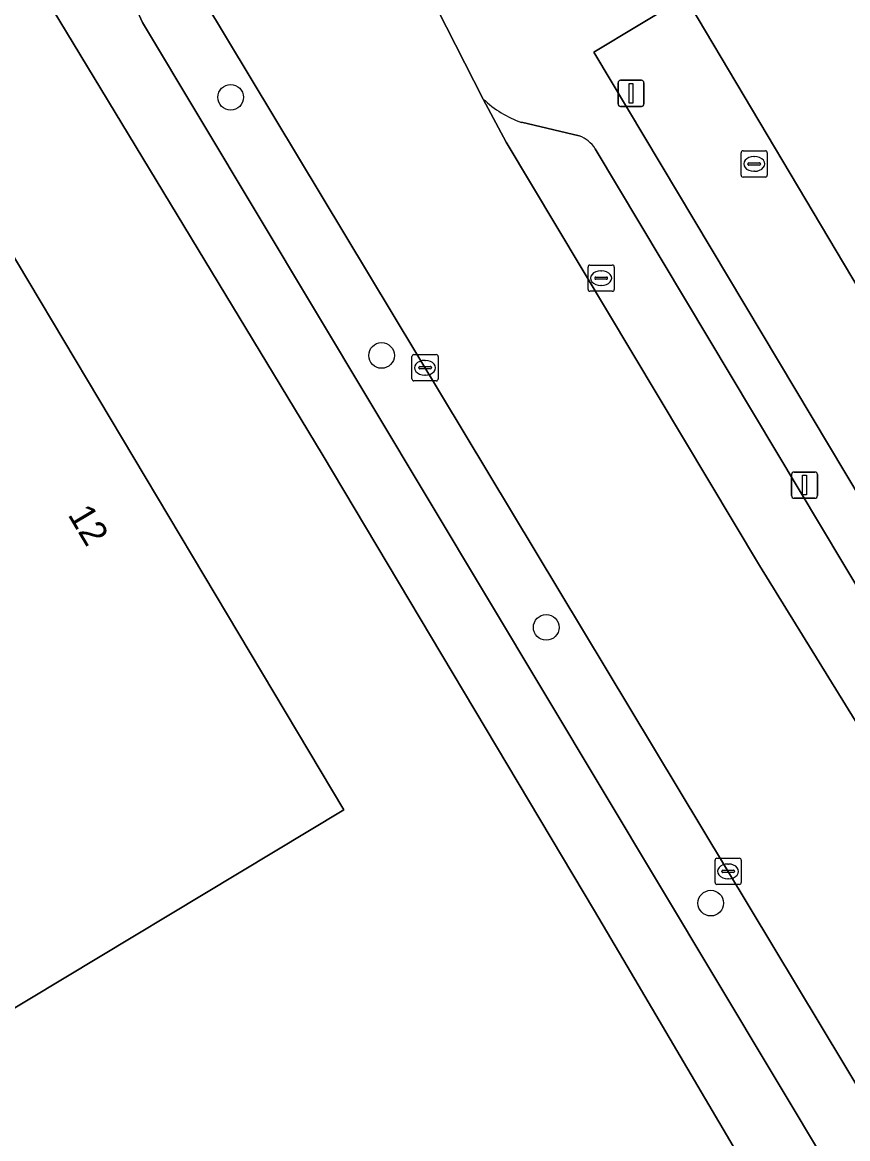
# Model space of a CAD drawing. Extents: x 156702 to 158052, y 387630 to 388992.
# Drawn here: x 157377.96 to 157409.43, y 388459.03 to 388501.62 of the extents above; entities that cross this region are included whole.
import ezdxf

# ---------------------------------------------------------------- set-up
doc = ezdxf.new("R2010")
doc.units = 0
for name, color, linetype in [('IMGEO_Boom', 7, 'Continuous'), ('IMGEO_Brandkraan', 7, 'Continuous'), ('IMGEO_Erf', 7, 'Continuous'), ('IMGEO_Groenvoorziening', 7, 'Continuous'), ('IMGEO_Hek', 7, 'Continuous'), ('IMGEO_Kolk', 7, 'Continuous'), ('IMGEO_Lichtmast', 7, 'Continuous'), ('IMGEO_Pand', 7, 'Continuous'), ('IMGEO_Pand_nummerreeks', 7, 'Continuous'), ('IMGEO_Parkeervlak_open', 7, 'Continuous'), ('IMGEO_Rijbaan_lokaal_gesloten', 7, 'Continuous'), ('IMGEO_Voetpad_open', 7, 'Continuous')]:
    doc.layers.add(name, color=color, linetype=linetype)

msp = doc.modelspace()

# ---------------------------------------------------------------- linework, layer by layer
at = {"layer": 'IMGEO_Boom'}
for centre in [(157385.902, 388498.761), (157391.656, 388488.912), (157397.932, 388478.539), (157404.207, 388468.019)]:
    msp.add_circle(centre, 0.489, dxfattribs=at)
at = {"layer": 'IMGEO_Brandkraan'}
for p, q in [((157405.362, 388495.793), (157405.362, 388496.645)), ((157405.437, 388496.719), (157406.289, 388496.719)), ((157405.85, 388496.499), (157405.875, 388496.499)), ((157406.363, 388496.645), (157406.363, 388495.793)), ((157405.621, 388496.213), (157405.621, 388496.225)), ((157406.059, 388496.176), (157405.661, 388496.176)), ((157405.664, 388496.262), (157406.062, 388496.262)), ((157405.873, 388495.939), (157405.848, 388495.939)), ((157406.105, 388496.225), (157406.105, 388496.213)), ((157406.289, 388495.719), (157405.437, 388495.719))]:
    msp.add_line(p, q, dxfattribs=at)
for points in [[(157405.362, 388495.793), (157405.362, 388496.645)], [(157405.437, 388496.719), (157406.289, 388496.719)], [(157406.363, 388496.645), (157406.363, 388495.793)], [(157406.289, 388495.719), (157405.437, 388495.719)]]:
    msp.add_lwpolyline(points, dxfattribs=at)
for centre, radius, start, end in [((157405.439, 388496.643), 0.0765, 91.552, 178.448), ((157405.439, 388496.643), 0.0765, 91.552, 178.448), ((157406.287, 388496.643), 0.0765, 1.552, 88.448), ((157406.287, 388496.643), 0.0765, 1.552, 88.448), ((157405.661, 388496.222), 0.0403, 85.8775, 175.7526), ((157405.658, 388496.212), 0.0366, 178.938, 274.7102), ((157406.062, 388496.219), 0.043, 264.8664, 352.4533), ((157406.066, 388496.224), 0.0386, 1.7309, 96.639), ((157405.439, 388495.795), 0.0765, 181.552, 268.448), ((157405.439, 388495.795), 0.0765, 181.552, 268.448), ((157406.287, 388495.795), 0.0765, 271.552, 358.448), ((157406.287, 388495.795), 0.0765, 271.552, 358.448)]:
    msp.add_arc(centre, radius, start, end, dxfattribs=at)
for centre, major_axis, ratio, start_param, end_param in [((157405.849, 388496.219), (-0.387, 0.002), 0.722429, 4.712389, 7.853982), ((157405.874, 388496.219), (-0.39, 0.002), 0.717154, 1.570796, 4.712389)]:
    msp.add_ellipse(centre, major_axis=major_axis, ratio=ratio, start_param=start_param, end_param=end_param, dxfattribs=at)
at = {"layer": 'IMGEO_Erf'}
msp.add_lwpolyline([(157317.179, 388395.086), (157324.683, 388396.936), (157373.801, 388408.213), (157379.547, 388409.463), (157379.563, 388409.386), (157380.626, 388409.68), (157387.6, 388411.288), (157389.06, 388411.591), (157389.005, 388411.792), (157395.197, 388413.239), (157408.08, 388416.25), (157427.8, 388420.86), (157416.517, 388439.8), (157410.746, 388449.094), (157401.022, 388465.621), (157399.772, 388467.72), (157389.391, 388485.151), (157376.205, 388506.903), (157374.126, 388505.416), (157373.371, 388506.57), (157367.622, 388505.382), (157366.586, 388505.546), (157337.64, 388497.99), (157297.332, 388486.579)], dxfattribs=at)
msp.add_lwpolyline([(157350.343, 388489.824), (157364.535, 388498.328), (157373.287, 388499.936), (157375.519, 388496.197), (157390.214, 388471.577), (157375.553, 388462.755), (157375.613, 388462.646), (157375.233, 388462.433), (157372.541, 388467.029), (157366.222, 388463.23), (157356.587, 388479.349), (157352.689, 388478.468), (157352.584, 388478.678), (157352.444, 388478.629), (157351.142, 388484.331), (157351.566, 388484.475), (157351.589, 388484.106), (157353.177, 388485.092)], close=True, dxfattribs=at)
at = {"layer": 'IMGEO_Groenvoorziening'}
msp.add_lwpolyline([(157400.773, 388506.727), (157400.598, 388507.022), (157400.594, 388506.913), (157400.55, 388506.883), (157403.127, 388502.525), (157399.747, 388500.478), (157432.385, 388445.838), (157433.586, 388443.796), (157435.209, 388444.735), (157437.003, 388445.772), (157436.88, 388445.978)], close=True, dxfattribs=at)
at = {"layer": 'IMGEO_Hek'}
msp.add_lwpolyline([(157437.003, 388445.772), (157436.88, 388445.978), (157400.773, 388506.727), (157400.598, 388507.022)], dxfattribs=at)
at = {"layer": 'IMGEO_Kolk'}
for p, q in [((157399.527, 388491.435), (157399.527, 388492.287)), ((157399.602, 388492.361), (157400.454, 388492.361)), ((157400.015, 388492.141), (157400.04, 388492.141)), ((157400.528, 388492.287), (157400.528, 388491.435)), ((157399.786, 388491.855), (157399.786, 388491.867)), ((157400.224, 388491.818), (157399.826, 388491.818)), ((157399.829, 388491.904), (157400.227, 388491.904)), ((157400.27, 388491.867), (157400.27, 388491.855)), ((157400.454, 388491.361), (157399.602, 388491.361)), ((157400.038, 388491.581), (157400.013, 388491.581)), ((157392.815, 388488.018), (157392.815, 388488.87)), ((157392.89, 388488.944), (157393.742, 388488.944)), ((157393.303, 388488.724), (157393.328, 388488.724)), ((157393.816, 388488.87), (157393.816, 388488.018)), ((157393.074, 388488.438), (157393.074, 388488.45)), ((157393.512, 388488.401), (157393.114, 388488.401)), ((157393.117, 388488.487), (157393.515, 388488.487)), ((157393.558, 388488.45), (157393.558, 388488.438)), ((157393.742, 388487.944), (157392.89, 388487.944)), ((157393.326, 388488.164), (157393.301, 388488.164)), ((157404.369, 388468.806), (157404.369, 388469.658)), ((157404.444, 388469.732), (157405.296, 388469.732)), ((157405.37, 388469.658), (157405.37, 388468.806)), ((157404.628, 388469.226), (157404.628, 388469.238)), ((157405.066, 388469.189), (157404.668, 388469.189)), ((157404.671, 388469.275), (157405.069, 388469.275)), ((157404.857, 388469.512), (157404.882, 388469.512)), ((157405.112, 388469.238), (157405.112, 388469.226)), ((157405.296, 388468.732), (157404.444, 388468.732)), ((157404.88, 388468.952), (157404.855, 388468.952))]:
    msp.add_line(p, q, dxfattribs=at)
for points in [[(157399.527, 388491.435), (157399.527, 388492.287)], [(157399.602, 388492.361), (157400.454, 388492.361)], [(157400.528, 388492.287), (157400.528, 388491.435)], [(157400.454, 388491.361), (157399.602, 388491.361)], [(157392.815, 388488.018), (157392.815, 388488.87)], [(157392.89, 388488.944), (157393.742, 388488.944)], [(157393.816, 388488.87), (157393.816, 388488.018)], [(157393.742, 388487.944), (157392.89, 388487.944)], [(157404.369, 388468.806), (157404.369, 388469.658)], [(157404.444, 388469.732), (157405.296, 388469.732)], [(157405.37, 388469.658), (157405.37, 388468.806)], [(157405.296, 388468.732), (157404.444, 388468.732)]]:
    msp.add_lwpolyline(points, dxfattribs=at)
for centre, radius, start, end in [((157399.604, 388492.285), 0.0765, 91.552, 178.448), ((157399.604, 388492.285), 0.0765, 91.552, 178.448), ((157400.452, 388492.285), 0.0765, 1.552, 88.448), ((157400.452, 388492.285), 0.0765, 1.552, 88.448), ((157399.826, 388491.864), 0.0403, 85.8775, 175.7526), ((157399.823, 388491.854), 0.0366, 178.938, 274.7102), ((157400.227, 388491.861), 0.043, 264.8664, 352.4533), ((157400.231, 388491.866), 0.0386, 1.7309, 96.639), ((157399.604, 388491.437), 0.0765, 181.552, 268.448), ((157399.604, 388491.437), 0.0765, 181.552, 268.448), ((157400.452, 388491.437), 0.0765, 271.552, 358.448), ((157400.452, 388491.437), 0.0765, 271.552, 358.448), ((157392.892, 388488.868), 0.0765, 91.552, 178.448), ((157392.892, 388488.868), 0.0765, 91.552, 178.448), ((157393.74, 388488.868), 0.0765, 1.552, 88.448), ((157393.74, 388488.868), 0.0765, 1.552, 88.448), ((157393.114, 388488.447), 0.0403, 85.8775, 175.7526), ((157393.111, 388488.437), 0.0366, 178.938, 274.7102), ((157393.515, 388488.444), 0.043, 264.8664, 352.4533), ((157393.519, 388488.449), 0.0386, 1.7309, 96.639), ((157392.892, 388488.02), 0.0765, 181.552, 268.448), ((157392.892, 388488.02), 0.0765, 181.552, 268.448), ((157393.74, 388488.02), 0.0765, 271.552, 358.448), ((157393.74, 388488.02), 0.0765, 271.552, 358.448), ((157404.446, 388469.656), 0.0765, 91.552, 178.448), ((157404.446, 388469.656), 0.0765, 91.552, 178.448), ((157405.294, 388469.656), 0.0765, 1.552, 88.448), ((157405.294, 388469.656), 0.0765, 1.552, 88.448), ((157404.668, 388469.235), 0.0403, 85.8775, 175.7526), ((157404.665, 388469.225), 0.0366, 178.938, 274.7102), ((157405.069, 388469.232), 0.043, 264.8664, 352.4533), ((157405.073, 388469.237), 0.0386, 1.7309, 96.639), ((157404.446, 388468.808), 0.0765, 181.552, 268.448), ((157404.446, 388468.808), 0.0765, 181.552, 268.448), ((157405.294, 388468.808), 0.0765, 271.552, 358.448), ((157405.294, 388468.808), 0.0765, 271.552, 358.448)]:
    msp.add_arc(centre, radius, start, end, dxfattribs=at)
for centre, major_axis, ratio, start_param, end_param in [((157400.014, 388491.861), (-0.387, 0.002), 0.722429, 4.712389, 7.853982), ((157400.039, 388491.861), (-0.39, 0.002), 0.717154, 1.570796, 4.712389), ((157393.302, 388488.444), (-0.387, 0.002), 0.722429, 4.712389, 7.853982), ((157393.327, 388488.444), (-0.39, 0.002), 0.717154, 1.570796, 4.712389), ((157404.856, 388469.232), (-0.387, 0.002), 0.722429, 4.712389, 7.853982), ((157404.881, 388469.232), (-0.39, 0.002), 0.717154, 1.570796, 4.712389)]:
    msp.add_ellipse(centre, major_axis=major_axis, ratio=ratio, start_param=start_param, end_param=end_param, dxfattribs=at)
at = {"layer": 'IMGEO_Lichtmast'}
for p, q in [((157400.771, 388499.411), (157401.561, 388499.411)), ((157401.561, 388499.411), (157400.771, 388499.411)), ((157400.671, 388498.511), (157400.671, 388499.311)), ((157400.671, 388499.311), (157400.671, 388498.511)), ((157401.661, 388499.311), (157401.661, 388498.511)), ((157401.661, 388498.511), (157401.661, 388499.311)), ((157401.561, 388498.411), (157400.771, 388498.411)), ((157400.771, 388498.411), (157401.561, 388498.411)), ((157407.387, 388484.465), (157408.177, 388484.465)), ((157408.177, 388484.465), (157407.387, 388484.465)), ((157407.287, 388483.565), (157407.287, 388484.365)), ((157407.287, 388484.365), (157407.287, 388483.565)), ((157408.277, 388484.365), (157408.277, 388483.565)), ((157408.277, 388483.565), (157408.277, 388484.365)), ((157408.177, 388483.465), (157407.387, 388483.465)), ((157407.387, 388483.465), (157408.177, 388483.465))]:
    msp.add_line(p, q, dxfattribs=at)
for points in [[(157401.091, 388499.286), (157401.241, 388499.286), (157401.241, 388498.536), (157401.091, 388498.536), (157401.091, 388499.286)], [(157407.707, 388484.34), (157407.857, 388484.34), (157407.857, 388483.59), (157407.707, 388483.59), (157407.707, 388484.34)]]:
    msp.add_lwpolyline(points, dxfattribs=at)
for centre, start, end in [((157400.771, 388499.311), 90, 180), ((157400.771, 388499.311), 90, 180), ((157401.561, 388499.311), 0, 90), ((157401.561, 388499.311), 360, 90), ((157400.771, 388498.511), 180, 270), ((157400.771, 388498.511), 180, 270), ((157401.561, 388498.511), 270, 0), ((157401.561, 388498.511), 270, 0), ((157407.387, 388484.365), 90, 180), ((157407.387, 388484.365), 90, 180), ((157408.177, 388484.365), 0, 90), ((157408.177, 388484.365), 360, 90), ((157407.387, 388483.565), 180, 270), ((157407.387, 388483.565), 180, 270), ((157408.177, 388483.565), 270, 0), ((157408.177, 388483.565), 270, 0)]:
    msp.add_arc(centre, 0.1, start, end, dxfattribs=at)
at = {"layer": 'IMGEO_Pand'}
msp.add_lwpolyline([(157364.535, 388498.328), (157350.343, 388489.824), (157353.177, 388485.092), (157351.589, 388484.106), (157351.566, 388484.475), (157351.142, 388484.331), (157352.444, 388478.629), (157352.584, 388478.678), (157352.689, 388478.468), (157356.587, 388479.349), (157366.222, 388463.23), (157372.541, 388467.029), (157375.233, 388462.433), (157375.613, 388462.646), (157375.553, 388462.755), (157390.214, 388471.577), (157375.519, 388496.197), (157373.287, 388499.936)], close=True, dxfattribs=at)
at = {"layer": 'IMGEO_Parkeervlak_open'}
msp.add_lwpolyline([(157405.996, 388509.831), (157400.773, 388506.727), (157436.88, 388445.978), (157442.103, 388449.082), (157426.4, 388475.502), (157410.729, 388501.867)], close=True, dxfattribs=at)
for points in [[(157383.032, 388505.544), (157382.296, 388502.573), (157382.297, 388502.147), (157382.545, 388501.61), (157408.813, 388457.752), (157413.653, 388449.828), (157418.749, 388441.074), (157426.614, 388427.868), (157427.224, 388427.414), (157429.48, 388426.914)], [(157430.755, 388426.017), (157421.092, 388442.257), (157383.032, 388505.544)], [(157395.535, 388498.696), (157396.411, 388497.052), (157406.064, 388480.897), (157423.836, 388452.097), (157427.382, 388445.752), (157428.669, 388443.598), (157430.832, 388444.891), (157399.804, 388496.799)], [(157399.193, 388497.289), (157396.992, 388497.806)]]:
    msp.add_lwpolyline(points, dxfattribs=at)
for centre, radius, start, end in [((157398.269, 388501.535), 3.942, 226.0734, 251.0898), ((157398.773, 388496.139), 1.224, 32.6101, 69.9332)]:
    msp.add_arc(centre, radius, start, end, dxfattribs=at)
at = {"layer": 'IMGEO_Rijbaan_lokaal_gesloten'}
for points in [[(157398.507, 388519.049), (157400.116, 388520.285), (157402.189, 388521.449), (157398.778, 388527.866), (157387.285, 388521.931), (157386.119, 388521.163), (157384.875, 388520.059), (157383.779, 388518.719), (157382.793, 388517.06), (157381.67, 388513.532), (157381.514, 388510.629), (157381.719, 388509.225), (157382.177, 388507.811), (157382.963, 388505.988), (157383.032, 388505.544), (157421.092, 388442.257), (157430.755, 388426.017), (157431.523, 388424.771)], [(157449.717, 388408.375), (157440.013, 388424.616), (157439.413, 388425.619), (157428.669, 388443.598), (157427.382, 388445.752), (157423.836, 388452.097), (157406.064, 388480.897), (157396.411, 388497.052), (157395.535, 388498.696), (157393.773, 388502.134), (157393.148, 388503.972), (157392.821, 388506.075), (157392.868, 388508.34), (157393.33, 388510.853), (157394.082, 388513.392), (157395.196, 388515.51), (157395.784, 388516.252), (157396.69, 388517.394), (157398.507, 388519.049)]]:
    msp.add_lwpolyline(points, dxfattribs=at)
at = {"layer": 'IMGEO_Voetpad_open'}
for points in [[(157399.747, 388500.478), (157403.127, 388502.525), (157400.55, 388506.883), (157395.784, 388516.252), (157395.196, 388515.51), (157394.082, 388513.392), (157393.33, 388510.853), (157392.868, 388508.34), (157392.821, 388506.075), (157393.148, 388503.972), (157393.773, 388502.134), (157395.535, 388498.696)], [(157382.545, 388501.61), (157382.297, 388502.147), (157382.296, 388502.573), (157383.032, 388505.544), (157376.146, 388508.593), (157376.205, 388506.903), (157389.391, 388485.151), (157399.772, 388467.72), (157401.022, 388465.621), (157410.746, 388449.094), (157416.517, 388439.8), (157427.8, 388420.86), (157428.182, 388419.584), (157430.186, 388416.435)], [(157429.48, 388426.914), (157427.224, 388427.414), (157426.614, 388427.868), (157418.749, 388441.074), (157413.653, 388449.828), (157408.813, 388457.752), (157382.545, 388501.61)], [(157399.804, 388496.799), (157430.832, 388444.891), (157432.385, 388445.838), (157399.747, 388500.478)], [(157396.992, 388497.806), (157399.193, 388497.289)]]:
    msp.add_lwpolyline(points, dxfattribs=at)
for centre, radius, start, end in [((157398.269, 388501.535), 3.942, 226.0734, 251.0898), ((157398.773, 388496.139), 1.224, 32.6101, 69.9332)]:
    msp.add_arc(centre, radius, start, end, dxfattribs=at)

# ---------------------------------------------------------------- texts
at = {"layer": 'IMGEO_Pand_nummerreeks'}
msp.add_text('12', height=1, rotation=300.8318, dxfattribs=at).set_placement((157379.672, 388482.84))

doc.saveas('drawing.dxf')
